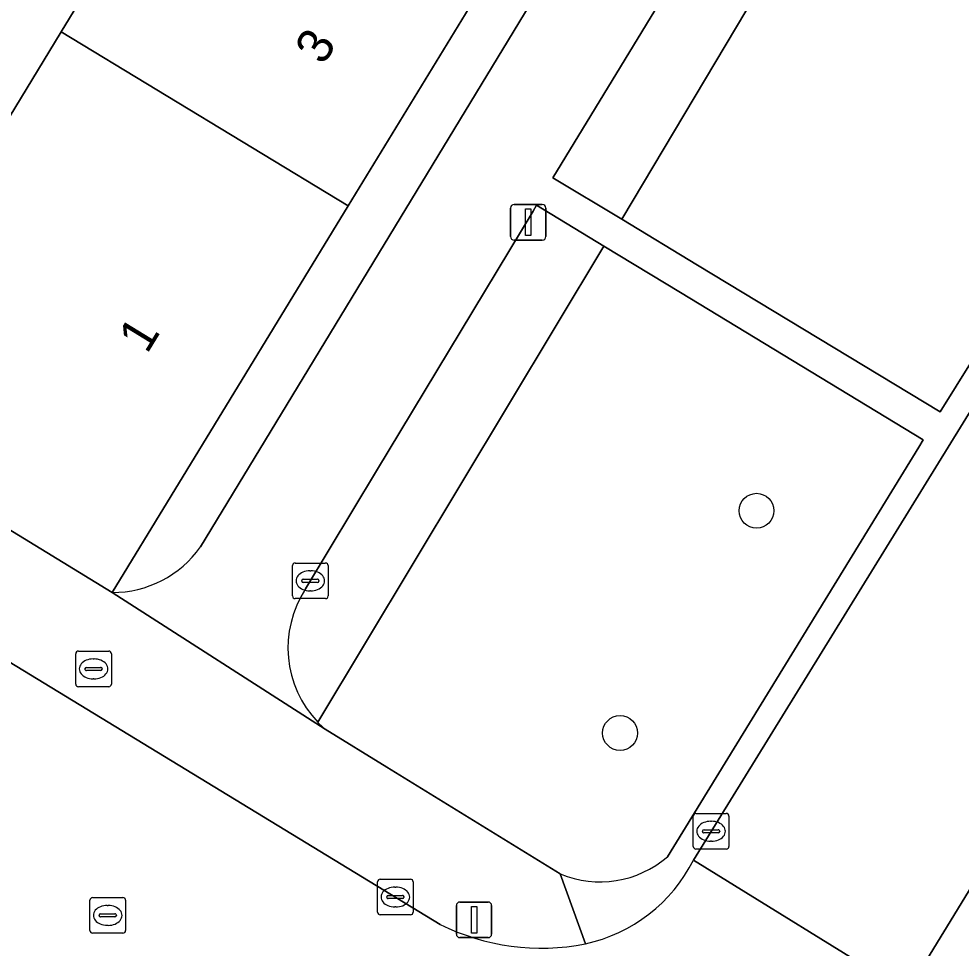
# Model space of a CAD drawing. Extents: x 158352 to 159489, y 383828 to 384603.
# Drawn here: x 158878.31 to 158904.75, y 383907.33 to 383933.42 of the extents above; entities that cross this region are included whole.
import ezdxf

# ---------------------------------------------------------------- set-up
doc = ezdxf.new("R2010")
doc.units = 0
for name, color, linetype in [('IMGEO_Boom', 7, 'Continuous'), ('IMGEO_Brandkraan', 7, 'Continuous'), ('IMGEO_Erf', 7, 'Continuous'), ('IMGEO_Fietspad_gesloten', 7, 'Continuous'), ('IMGEO_Groenvoorziening', 7, 'Continuous'), ('IMGEO_Kolk', 7, 'Continuous'), ('IMGEO_Lichtmast', 7, 'Continuous'), ('IMGEO_Pand', 7, 'Continuous'), ('IMGEO_Pand_nummerreeks', 7, 'Continuous'), ('IMGEO_Rijbaan_lokaal_open', 7, 'Continuous'), ('IMGEO_Rioolput', 7, 'Continuous'), ('IMGEO_Voetpad_open', 7, 'Continuous')]:
    doc.layers.add(name, color=color, linetype=linetype)

msp = doc.modelspace()

# ---------------------------------------------------------------- linework, layer by layer
at = {"layer": 'IMGEO_Boom'}
for centre in [(158899.007, 383919.61), (158895.178, 383913.371)]:
    msp.add_circle(centre, 0.489, dxfattribs=at)
at = {"layer": 'IMGEO_Brandkraan'}
for p, q in [((158879.907, 383914.744), (158879.907, 383915.596)), ((158879.982, 383915.67), (158880.834, 383915.67)), ((158880.908, 383915.596), (158880.908, 383914.744)), ((158880.395, 383915.45), (158880.42, 383915.45)), ((158880.166, 383915.164), (158880.166, 383915.176)), ((158880.604, 383915.127), (158880.206, 383915.127)), ((158880.209, 383915.213), (158880.607, 383915.213)), ((158880.65, 383915.176), (158880.65, 383915.164)), ((158880.418, 383914.89), (158880.393, 383914.89)), ((158880.834, 383914.67), (158879.982, 383914.67))]:
    msp.add_line(p, q, dxfattribs=at)
for points in [[(158879.907, 383914.744), (158879.907, 383915.596)], [(158879.982, 383915.67), (158880.834, 383915.67)], [(158880.908, 383915.596), (158880.908, 383914.744)], [(158880.834, 383914.67), (158879.982, 383914.67)]]:
    msp.add_lwpolyline(points, dxfattribs=at)
for centre, radius, start, end in [((158879.984, 383915.594), 0.0765, 91.552, 178.448), ((158879.984, 383915.594), 0.0765, 91.552, 178.448), ((158880.832, 383915.594), 0.0765, 1.552, 88.448), ((158880.832, 383915.594), 0.0765, 1.552, 88.448), ((158880.206, 383915.173), 0.0403, 85.8775, 175.7526), ((158880.203, 383915.163), 0.0366, 178.938, 274.7102), ((158880.607, 383915.17), 0.043, 264.8664, 352.4533), ((158880.611, 383915.175), 0.0386, 1.7309, 96.639), ((158879.984, 383914.746), 0.0765, 181.552, 268.448), ((158879.984, 383914.746), 0.0765, 181.552, 268.448), ((158880.832, 383914.746), 0.0765, 271.552, 358.448), ((158880.832, 383914.746), 0.0765, 271.552, 358.448)]:
    msp.add_arc(centre, radius, start, end, dxfattribs=at)
for centre, major_axis, ratio, start_param, end_param in [((158880.394, 383915.17), (-0.387, 0.002), 0.722429, 4.712389, 7.853982), ((158880.419, 383915.17), (-0.39, 0.002), 0.717154, 1.570796, 4.712389)]:
    msp.add_ellipse(centre, major_axis=major_axis, ratio=ratio, start_param=start_param, end_param=end_param, dxfattribs=at)
at = {"layer": 'IMGEO_Erf'}
for points in [[(158883.405, 383918.597), (158907.345, 383958.034), (158906.428, 383959.075), (158900.426, 383965.889)], [(158889.673, 383949.784), (158893.109, 383955.435), (158896.618, 383961.1), (158904.665, 383956.197), (158901.193, 383950.527), (158897.749, 383944.881), (158894.344, 383939.3), (158890.945, 383933.729), (158887.551, 383928.166), (158880.931, 383917.315)], [(158872.913, 383922.218), (158879.501, 383933.053), (158882.886, 383938.621), (158886.276, 383944.197), (158889.673, 383949.784)]]:
    msp.add_lwpolyline(points, dxfattribs=at)
msp.add_arc((158880.938, 383920.33), 3.015, 269.8662, 324.9192, dxfattribs=at)
at = {"layer": 'IMGEO_Fietspad_gesloten'}
msp.add_lwpolyline([(158907.235, 383912.655), (158903.472, 383906.489)], dxfattribs=at)
at = {"layer": 'IMGEO_Groenvoorziening'}
for points in [[(158902.82, 383940.551), (158901.018, 383941.655), (158900.911, 383941.478), (158893.291, 383928.959), (158895.225, 383927.79)], [(158911.974, 383934.943), (158905.154, 383939.121), (158902.82, 383940.551), (158895.225, 383927.79), (158897.351, 383926.504), (158904.157, 383922.389)]]:
    msp.add_lwpolyline(points, close=True, dxfattribs=at)
for points in [[(158894.721, 383927.04), (158892.838, 383928.183), (158892.737, 383928.015), (158888.348, 383920.729), (158886.353, 383917.416)], [(158886.699, 383913.671), (158894.721, 383927.04)], [(158903.563, 383921.395), (158903.687, 383921.597), (158896.872, 383925.735), (158894.721, 383927.04), (158886.699, 383913.671)], [(158896.508, 383909.897), (158903.563, 383921.395)], [(158886.902, 383913.477), (158888.633, 383912.412), (158893.501, 383909.418)]]:
    msp.add_lwpolyline(points, dxfattribs=at)
for centre, radius, start, end in [((158888.893, 383915.762), 3.031, 146.9299, 223.6273), ((158888.547, 383915.401), 2.532, 223.1195, 229.4779), ((158894.617, 383912.087), 2.893, 247.3017, 310.8001)]:
    msp.add_arc(centre, radius, start, end, dxfattribs=at)
at = {"layer": 'IMGEO_Kolk'}
for p, q in [((158885.987, 383917.217), (158885.987, 383918.069)), ((158886.062, 383918.143), (158886.914, 383918.143)), ((158886.988, 383918.069), (158886.988, 383917.217)), ((158886.475, 383917.923), (158886.5, 383917.923)), ((158886.246, 383917.637), (158886.246, 383917.649)), ((158886.684, 383917.6), (158886.286, 383917.6)), ((158886.289, 383917.686), (158886.687, 383917.686)), ((158886.73, 383917.649), (158886.73, 383917.637)), ((158886.498, 383917.363), (158886.473, 383917.363)), ((158886.914, 383917.143), (158886.062, 383917.143)), ((158897.307, 383911.113), (158898.159, 383911.113)), ((158897.232, 383910.187), (158897.232, 383911.039)), ((158897.72, 383910.893), (158897.745, 383910.893)), ((158898.233, 383911.039), (158898.233, 383910.187)), ((158897.491, 383910.607), (158897.491, 383910.619)), ((158897.929, 383910.57), (158897.531, 383910.57)), ((158897.534, 383910.656), (158897.932, 383910.656)), ((158897.975, 383910.619), (158897.975, 383910.607)), ((158897.743, 383910.333), (158897.718, 383910.333)), ((158898.159, 383910.113), (158897.307, 383910.113)), ((158888.449, 383909.267), (158889.301, 383909.267)), ((158888.374, 383908.341), (158888.374, 383909.193)), ((158888.862, 383909.047), (158888.887, 383909.047)), ((158889.375, 383909.193), (158889.375, 383908.341)), ((158888.633, 383908.761), (158888.633, 383908.773)), ((158889.071, 383908.724), (158888.673, 383908.724)), ((158888.676, 383908.81), (158889.074, 383908.81)), ((158889.117, 383908.773), (158889.117, 383908.761)), ((158888.885, 383908.487), (158888.86, 383908.487)), ((158889.301, 383908.267), (158888.449, 383908.267))]:
    msp.add_line(p, q, dxfattribs=at)
for points in [[(158885.987, 383917.217), (158885.987, 383918.069)], [(158886.062, 383918.143), (158886.914, 383918.143)], [(158886.988, 383918.069), (158886.988, 383917.217)], [(158886.914, 383917.143), (158886.062, 383917.143)], [(158897.307, 383911.113), (158898.159, 383911.113)], [(158897.232, 383910.187), (158897.232, 383911.039)], [(158898.233, 383911.039), (158898.233, 383910.187)], [(158898.159, 383910.113), (158897.307, 383910.113)], [(158888.449, 383909.267), (158889.301, 383909.267)], [(158888.374, 383908.341), (158888.374, 383909.193)], [(158889.375, 383909.193), (158889.375, 383908.341)], [(158889.301, 383908.267), (158888.449, 383908.267)]]:
    msp.add_lwpolyline(points, dxfattribs=at)
for centre, radius, start, end in [((158886.064, 383918.067), 0.0765, 91.552, 178.448), ((158886.064, 383918.067), 0.0765, 91.552, 178.448), ((158886.912, 383918.067), 0.0765, 1.552, 88.448), ((158886.912, 383918.067), 0.0765, 1.552, 88.448), ((158886.286, 383917.646), 0.0403, 85.8775, 175.7526), ((158886.283, 383917.636), 0.0366, 178.938, 274.7102), ((158886.687, 383917.643), 0.043, 264.8664, 352.4533), ((158886.691, 383917.648), 0.0386, 1.7309, 96.639), ((158886.064, 383917.219), 0.0765, 181.552, 268.448), ((158886.064, 383917.219), 0.0765, 181.552, 268.448), ((158886.912, 383917.219), 0.0765, 271.552, 358.448), ((158886.912, 383917.219), 0.0765, 271.552, 358.448), ((158897.309, 383911.037), 0.0765, 91.552, 178.448), ((158897.309, 383911.037), 0.0765, 91.552, 178.448), ((158898.157, 383911.037), 0.0765, 1.552, 88.448), ((158898.157, 383911.037), 0.0765, 1.552, 88.448), ((158897.531, 383910.616), 0.0403, 85.8775, 175.7526), ((158897.528, 383910.606), 0.0366, 178.938, 274.7102), ((158897.932, 383910.613), 0.043, 264.8664, 352.4533), ((158897.936, 383910.618), 0.0386, 1.7309, 96.639), ((158897.309, 383910.189), 0.0765, 181.552, 268.448), ((158897.309, 383910.189), 0.0765, 181.552, 268.448), ((158898.157, 383910.189), 0.0765, 271.552, 358.448), ((158898.157, 383910.189), 0.0765, 271.552, 358.448), ((158888.451, 383909.191), 0.0765, 91.552, 178.448), ((158888.451, 383909.191), 0.0765, 91.552, 178.448), ((158889.299, 383909.191), 0.0765, 1.552, 88.448), ((158889.299, 383909.191), 0.0765, 1.552, 88.448), ((158888.673, 383908.77), 0.0403, 85.8775, 175.7526), ((158888.67, 383908.76), 0.0366, 178.938, 274.7102), ((158889.074, 383908.767), 0.043, 264.8664, 352.4533), ((158889.078, 383908.772), 0.0386, 1.7309, 96.639), ((158888.451, 383908.343), 0.0765, 181.552, 268.448), ((158888.451, 383908.343), 0.0765, 181.552, 268.448), ((158889.299, 383908.343), 0.0765, 271.552, 358.448), ((158889.299, 383908.343), 0.0765, 271.552, 358.448)]:
    msp.add_arc(centre, radius, start, end, dxfattribs=at)
for centre, major_axis, ratio, start_param, end_param in [((158886.474, 383917.643), (-0.387, 0.002), 0.722429, 4.712389, 7.853982), ((158886.499, 383917.643), (-0.39, 0.002), 0.717154, 1.570796, 4.712389), ((158897.719, 383910.613), (-0.387, 0.002), 0.722429, 4.712389, 7.853982), ((158897.744, 383910.613), (-0.39, 0.002), 0.717154, 1.570796, 4.712389), ((158888.861, 383908.767), (-0.387, 0.002), 0.722429, 4.712389, 7.853982), ((158888.886, 383908.767), (-0.39, 0.002), 0.717154, 1.570796, 4.712389)]:
    msp.add_ellipse(centre, major_axis=major_axis, ratio=ratio, start_param=start_param, end_param=end_param, dxfattribs=at)
at = {"layer": 'IMGEO_Lichtmast'}
for p, q in [((158892.107, 383927.307), (158892.107, 383928.107)), ((158892.107, 383928.107), (158892.107, 383927.307)), ((158892.207, 383928.207), (158892.997, 383928.207)), ((158892.997, 383928.207), (158892.207, 383928.207)), ((158893.097, 383928.107), (158893.097, 383927.307)), ((158893.097, 383927.307), (158893.097, 383928.107)), ((158892.997, 383927.207), (158892.207, 383927.207)), ((158892.207, 383927.207), (158892.997, 383927.207)), ((158890.586, 383907.727), (158890.586, 383908.527)), ((158890.586, 383908.527), (158890.586, 383907.727)), ((158890.686, 383908.627), (158891.476, 383908.627)), ((158891.476, 383908.627), (158890.686, 383908.627)), ((158891.576, 383908.527), (158891.576, 383907.727)), ((158891.576, 383907.727), (158891.576, 383908.527)), ((158891.476, 383907.627), (158890.686, 383907.627)), ((158890.686, 383907.627), (158891.476, 383907.627))]:
    msp.add_line(p, q, dxfattribs=at)
for points in [[(158892.527, 383928.082), (158892.677, 383928.082), (158892.677, 383927.332), (158892.527, 383927.332), (158892.527, 383928.082)], [(158891.006, 383908.502), (158891.156, 383908.502), (158891.156, 383907.752), (158891.006, 383907.752), (158891.006, 383908.502)]]:
    msp.add_lwpolyline(points, dxfattribs=at)
for centre, start, end in [((158892.207, 383928.107), 90, 180), ((158892.207, 383928.107), 90, 180), ((158892.997, 383928.107), 0, 90), ((158892.997, 383928.107), 360, 90), ((158892.207, 383927.307), 180, 270), ((158892.207, 383927.307), 180, 270), ((158892.997, 383927.307), 270, 0), ((158892.997, 383927.307), 270, 0), ((158890.686, 383908.527), 90, 180), ((158890.686, 383908.527), 90, 180), ((158891.476, 383908.527), 0, 90), ((158891.476, 383908.527), 360, 90), ((158890.686, 383907.727), 180, 270), ((158890.686, 383907.727), 180, 270), ((158891.476, 383907.727), 270, 0), ((158891.476, 383907.727), 270, 0)]:
    msp.add_arc(centre, 0.1, start, end, dxfattribs=at)
at = {"layer": 'IMGEO_Pand'}
for points in [[(158879.501, 383933.053), (158887.551, 383928.166), (158890.945, 383933.729), (158882.886, 383938.621)], [(158879.501, 383933.053), (158872.913, 383922.218), (158880.931, 383917.315), (158887.551, 383928.166)]]:
    msp.add_lwpolyline(points, close=True, dxfattribs=at)
at = {"layer": 'IMGEO_Rijbaan_lokaal_open'}
for points in [[(158930.218, 383952.85), (158916.322, 383940.83), (158914.449, 383937.728), (158897.239, 383909.803), (158903.232, 383906.095), (158903.472, 383906.489), (158907.235, 383912.655), (158908.251, 383914.287), (158910.656, 383918.081)], [(158890.133, 383907.999), (158877.427, 383915.735), (158872.704, 383907.882), (158876.427, 383905.616)], [(158903.232, 383906.095), (158897.239, 383909.803)]]:
    msp.add_lwpolyline(points, dxfattribs=at)
for centre, radius, start, end in [((158893.258, 383911.812), 4.459, 282.2662, 333.2297), ((158892.969, 383913.706), 6.373, 243.5736, 281.1799)]:
    msp.add_arc(centre, radius, start, end, dxfattribs=at)
at = {"layer": 'IMGEO_Rioolput'}
for p, q in [((158880.379, 383908.752), (158881.231, 383908.752)), ((158880.304, 383907.826), (158880.304, 383908.678)), ((158880.792, 383908.532), (158880.817, 383908.532)), ((158881.305, 383908.678), (158881.305, 383907.826)), ((158880.563, 383908.246), (158880.563, 383908.258)), ((158881.001, 383908.209), (158880.603, 383908.209)), ((158880.606, 383908.295), (158881.004, 383908.295)), ((158881.047, 383908.258), (158881.047, 383908.246)), ((158880.815, 383907.972), (158880.79, 383907.972)), ((158881.231, 383907.752), (158880.379, 383907.752))]:
    msp.add_line(p, q, dxfattribs=at)
for points in [[(158880.379, 383908.752), (158881.231, 383908.752)], [(158880.304, 383907.826), (158880.304, 383908.678)], [(158881.305, 383908.678), (158881.305, 383907.826)], [(158881.231, 383907.752), (158880.379, 383907.752)]]:
    msp.add_lwpolyline(points, dxfattribs=at)
for centre, radius, start, end in [((158880.381, 383908.676), 0.0765, 91.552, 178.448), ((158880.381, 383908.676), 0.0765, 91.552, 178.448), ((158881.229, 383908.676), 0.0765, 1.552, 88.448), ((158881.229, 383908.676), 0.0765, 1.552, 88.448), ((158880.603, 383908.255), 0.0403, 85.8775, 175.7526), ((158880.6, 383908.245), 0.0366, 178.938, 274.7102), ((158881.004, 383908.252), 0.043, 264.8664, 352.4533), ((158881.008, 383908.257), 0.0386, 1.7309, 96.639), ((158880.381, 383907.828), 0.0765, 181.552, 268.448), ((158880.381, 383907.828), 0.0765, 181.552, 268.448), ((158881.229, 383907.828), 0.0765, 271.552, 358.448), ((158881.229, 383907.828), 0.0765, 271.552, 358.448)]:
    msp.add_arc(centre, radius, start, end, dxfattribs=at)
for centre, major_axis, ratio, start_param, end_param in [((158880.791, 383908.252), (-0.387, 0.002), 0.722429, 4.712389, 7.853982), ((158880.816, 383908.252), (-0.39, 0.002), 0.717154, 1.570796, 4.712389)]:
    msp.add_ellipse(centre, major_axis=major_axis, ratio=ratio, start_param=start_param, end_param=end_param, dxfattribs=at)
at = {"layer": 'IMGEO_Voetpad_open'}
for points in [[(158908.587, 383961.89), (158906.428, 383959.075), (158907.345, 383958.034), (158883.405, 383918.597)], [(158811.929, 383955.585), (158825.751, 383947.179), (158828.048, 383945.782), (158849.664, 383932.637), (158875.147, 383917.123), (158877.427, 383915.735), (158890.133, 383907.999)], [(158894.205, 383907.454), (158893.501, 383909.418), (158888.633, 383912.412), (158886.902, 383913.477), (158880.931, 383917.315), (158872.913, 383922.218), (158865.975, 383926.38), (158865.759, 383926.51), (158865.658, 383926.571), (158864.328, 383927.368), (158832.465, 383946.483)], [(158897.239, 383909.803), (158914.449, 383937.728), (158916.322, 383940.83)], [(158886.353, 383917.416), (158888.348, 383920.729), (158892.737, 383928.015), (158892.838, 383928.183), (158894.721, 383927.04), (158896.872, 383925.735), (158903.687, 383921.597), (158903.563, 383921.395), (158896.508, 383909.897)], [(158880.931, 383917.315), (158886.902, 383913.477)], [(158893.501, 383909.418), (158894.205, 383907.454)]]:
    msp.add_lwpolyline(points, dxfattribs=at)
msp.add_lwpolyline([(158911.974, 383934.943), (158904.157, 383922.389), (158897.351, 383926.504), (158895.225, 383927.79), (158893.291, 383928.959), (158900.911, 383941.478), (158901.018, 383941.655), (158902.82, 383940.551), (158905.154, 383939.121)], close=True, dxfattribs=at)
for centre, radius, start, end in [((158880.938, 383920.33), 3.015, 269.8662, 324.9192), ((158888.893, 383915.762), 3.031, 146.9299, 223.6273), ((158888.547, 383915.401), 2.532, 223.1195, 229.4779), ((158894.617, 383912.087), 2.893, 247.3017, 310.8001), ((158893.258, 383911.812), 4.459, 282.2662, 333.2297), ((158892.969, 383913.706), 6.373, 243.5736, 281.1799)]:
    msp.add_arc(centre, radius, start, end, dxfattribs=at)

# ---------------------------------------------------------------- texts
at = {"layer": 'IMGEO_Pand_nummerreeks'}
for s, rotation, p in [('3', 58.6574, (158886.856, 383932.088)), ('1', 58.5403, (158881.906, 383923.988))]:
    msp.add_text(s, height=1, rotation=rotation, dxfattribs=at).set_placement(p)

doc.saveas('drawing.dxf')
